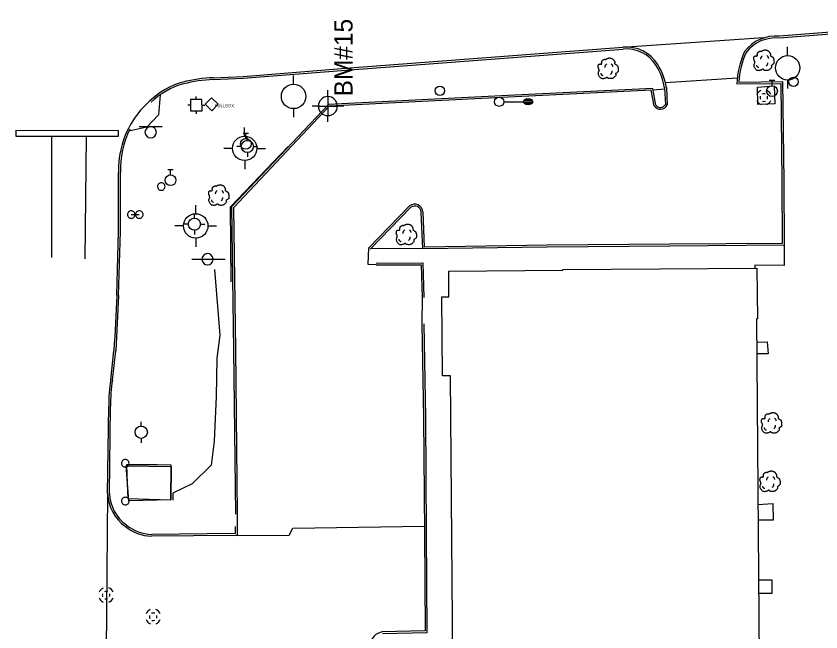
# Model space of a CAD drawing. Extents: x 2145380 to 2157287, y 139568 to 149130.
# Drawn here: x 2145641 to 2145904.9, y 142715.7 to 142917.6 of the extents above; entities that cross this region are included whole.
import ezdxf

# ---------------------------------------------------------------- set-up
doc = ezdxf.new("R2010")
doc.units = 0
for name, color, linetype in [('Default', 7, 'Continuous'), ('SURV_Benchmark', 7, 'Continuous'), ('TOPO_Asphalt', 7, 'Continuous'), ('TOPO_Building', 7, 'Continuous'), ('TOPO_Concrete', 7, 'Continuous'), ('TOPO_Curb Back', 7, 'Continuous'), ('TOPO_DRAIN_Inlet Grate', 7, 'Continuous'), ('TOPO_DRAIN_Manhole', 7, 'Continuous'), ('TOPO_Flowline', 7, 'Continuous'), ('TOPO_Light Pole', 7, 'Continuous'), ('TOPO_Misc', 7, 'Continuous'), ('TOPO_Misc Line', 7, 'Continuous'), ('TOPO_Power Pole', 7, 'Continuous'), ('TOPO_Power Pullbox', 7, 'Continuous'), ('TOPO_Sidewalk', 7, 'Continuous'), ('TOPO_Sign', 7, 'Continuous'), ('TOPO_Traffic Signal', 7, 'Continuous'), ('TOPO_Tree', 7, 'Continuous'), ('TOPO_Wall Freestanding', 7, 'Continuous'), ('TOPO_Water Fire Hydrant', 7, 'Continuous'), ('TOPO_Water Meter', 7, 'Continuous'), ('TOPO_Water Valve', 7, 'Continuous')]:
    doc.layers.add(name, color=color, linetype=linetype)

# ---------------------------------------------------------------- blocks, each defined once
blk = doc.blocks.new('MHEXST')
at = {"layer": 'TOPO_DRAIN_Manhole'}
for centre, radius, start, end in [((-0.1, 0.3), 12.7, 112.9748, 158.2636), ((-0.1, 0.1), 6.35, 157.9722, 204.161), ((-0.1, 0.1), 6.35, 66.1941, 113.691), ((-0.1, 0.3), 12.7, 22.0744, 68.6991), ((-0.1, 0.1), 6.35, 336.8023, 21.4046), ((-0.1, 0.3), 12.7, 202.6921, 248.1938), ((-0.1, 0.1), 6.35, 248.5791, 293.1995), ((-0.1, 0.3), 12.7, 291.7963, 337.3032)]:
    blk.add_arc(centre, radius, start, end, dxfattribs=at)
blk = doc.blocks.new('TRFSIG')
at = {"layer": 'TOPO_Traffic Signal'}
for p, q in [((0.04, 4.66), (0.04, 7.04)), ((-4.7, -0.09), (-7.08, -0.09)), ((0.04, -4.83), (0.04, -7.22)), ((4.79, -0.09), (7.17, -0.09))]:
    blk.add_line(p, q, dxfattribs=at)
blk.add_lwpolyline([(-4.7, -4.85), (4.81, -4.83), (4.79, 4.67), (-4.72, 4.66), (-4.7, -4.85)], dxfattribs=at)
blk = doc.blocks.new('FIRHYD')
at = {"layer": 'TOPO_Water Fire Hydrant'}
for p, q in [((-0.02, 10.16), (-0.03, 17.34)), ((10.16, 0.02), (17.34, 0.03)), ((-10.16, -0.02), (-17.34, -0.03)), ((0.02, -10.16), (0.03, -17.34))]:
    blk.add_line(p, q, dxfattribs=at)
blk.add_circle((0, 0), 10.16, dxfattribs=at)
blk = doc.blocks.new('POST')
at = {"layer": 'TOPO_Misc'}
for start, end in [(89.99996, 180.00004), (179.99996, 270.00004), (359.99996, 90.00004), (269.99996, 0.00004)]:
    blk.add_arc((-0.01, 0.03), 3.16, start, end, dxfattribs=at)
blk = doc.blocks.new('POWPOL')
at = {"layer": 'TOPO_Power Pole'}
for p, q in [((0, 10.16), (0, 17.34)), ((0, -10.16), (0, -17.34))]:
    blk.add_line(p, q, dxfattribs=at)
blk.add_circle((0, 0), 10.16, dxfattribs=at)
blk = doc.blocks.new('LP')
at = {"layer": 'TOPO_Light Pole'}
blk.add_line((3.81, 0), (20.32, 0), dxfattribs=at)
for points in [[(20.32, 0), (27.94, 0)], [(20.32, 0), (23.5, 0)], [(20.83, 1.27), (27.43, 1.27)], [(20.83, 1.27), (23.5, 1.27)], [(23.71, 1.27), (27.43, 1.27)], [(23.71, 0), (27.94, 0)], [(20.83, -1.27), (27.43, -1.27)], [(20.83, -1.27), (23.5, -1.27)], [(23.71, -1.27), (27.43, -1.27)]]:
    blk.add_lwpolyline(points, dxfattribs=at)
blk.add_circle((0, 0), 3.81, dxfattribs=at)
blk.add_ellipse((24.13, 0), major_axis=(3.81, 0), ratio=0.666667, dxfattribs=at)
blk = doc.blocks.new('TREE')
at = {"layer": 'TOPO_Tree'}
for points in [[(-14.1, -0.4), (-14.2, 0.5), (-14.4, 1.4), (-14.6, 2.3), (-14.8, 3.2), (-15.5, 4), (-15.7, 4.9), (-15.8, 5.6), (-15.7, 6.3), (-15.7, 7), (-15.6, 7.9), (-15.7, 8.8), (-15.1, 9.7), (-14.6, 10.4), (-13.8, 10.5), (-13, 10.7), (-12.2, 11), (-11.1, 10), (-10.4, 10.7), (-9.4, 11.7), (-10.3, 13.3), (-9.8, 14.4), (-9.6, 15.1), (-9.3, 15.9), (-8.8, 16.5), (-8.2, 17.3), (-7.5, 17.7), (-6.7, 18.1), (-6.1, 18.4), (-5.6, 18.6), (-5.1, 18.7), (-4.5, 18.7), (-4, 18.5), (-3.5, 18.1)], [(-3.5, 17.6), (-3.1, 18.3), (-2.6, 18.8), (-1.9, 19.2), (-1, 19.7), (-0.2, 20), (0.7, 20.2), (1.6, 20.5), (2.5, 20.8), (3.4, 20.8), (4.1, 20.7), (4.8, 20.5), (5.5, 20.2), (6.4, 19.9), (7.3, 19.7), (8.2, 19.2), (9.4, 18.4), (10, 17.2), (10.8, 16), (11.2, 15.3), (11.6, 14.6), (11.9, 13.9), (12.2, 13.1), (11.4, 12), (11.9, 11.2), (12, 11), (12.2, 10.9), (12.4, 10.7), (12.9, 10.4), (13.5, 10), (14, 9.7), (14.7, 9.2), (15.4, 8.7), (16.1, 8.1), (16.7, 7.5), (16.9, 6.7), (17.1, 6), (17.6, 4.4), (17.7, 2.8), (17.7, 1.2), (17.7, -0.2), (17.8, -2.2), (16.6, -3), (15.5, -3.8), (14.3, -4.6), (13.2, -5.3)], [(13.2, -5.3), (13.3, -5.8), (13.4, -6.3), (13.4, -6.7), (13.8, -8.5), (12.2, -10), (10.8, -11.5), (10, -12.3), (9.1, -12.8), (8.2, -13.1), (6, -13.8), (3.3, -13.6), (1.3, -13.1), (0.5, -12.9), (-0.1, -11.4), (-0.8, -11.5), (-2, -11.6), (-3.3, -12.8), (-4.5, -13.1), (-6.1, -13.5), (-7.8, -14), (-9.3, -13.6), (-11.4, -13.1), (-12.8, -11.4), (-14.1, -9.4), (-15.3, -7.3), (-15.6, -5.1), (-15.1, -3), (-14.9, -1.9), (-13.9, -0.8), (-13.5, 0.1)], [(-4.2, 5.1), (-4.5, 6.1), (-4.3, 7.2), (-3.8, 8.2), (-3.3, 9.3), (-2.7, 10.3), (-1.6, 11)], [(5.9, 11.2), (6.5, 10.7), (7, 10.2), (7.4, 9.5), (7.9, 8.6), (8.3, 7.6), (8.5, 6.6)], [(-11.4, -4.5), (-11.5, -5.4), (-11, -6.3), (-10.1, -7.2), (-9.3, -8), (-8.5, -8.3), (-7.7, -8.1)], [(4.8, -6.3), (5.7, -5.7), (6.3, -4.9), (6.8, -3.9), (7.4, -2.8), (7.6, -1.7), (7.5, -0.6)]]:
    blk.add_open_spline(points, degree=3, dxfattribs=at)
blk = doc.blocks.new('pulbox')
at = {"layer": 'Default'}
blk.add_lwpolyline([(-5.38, -0.01), (-0.02, 5.42), (5.4, 0.06), (0.05, -5.36), (-5.38, -0.01)], dxfattribs=at)
blk.add_text('PULLBOX', height=2.54, dxfattribs=at).set_placement((2.54, -2.54))
blk = doc.blocks.new('WTRMTR')
at = {"layer": 'Default'}
blk.add_circle((0, 0), 3.89, dxfattribs=at)
blk = doc.blocks.new('WATVAL')
at = {"layer": 'Default'}
for p, q in [((-2.25, 9), (2.25, 9)), ((0, 4.5), (0, 9))]:
    blk.add_line(p, q, dxfattribs=at)
blk.add_circle((0, 0), 4.5, dxfattribs=at)
blk = doc.blocks.new('BM')
at = {"layer": 'SURV_Benchmark'}
for p, q in [((0, 2.49), (0, 4.15)), ((-2.49, 0), (-4.16, 0)), ((4.16, 0), (2.49, 0)), ((0, -4.16), (0, -2.49))]:
    blk.add_line(p, q, dxfattribs=at)
for points in [[(0, 2.49), (0, 2.49), (0, 0), (2.49, 0), (2.49, 0), (2.49, 0)], [(0, 2.49), (0, 2.49), (0, 0), (2.49, 0), (2.49, 0), (2.49, 0), (2.49, 0)], [(-2.5, 0), (-2.49, 0), (0, 0), (0, -2.49), (0, -2.49)], [(-2.5, 0), (-2.49, 0), (0, 0), (0, -2.49), (0, -2.49)]]:
    blk.add_lwpolyline(points, dxfattribs=at)
for start, end in [(90.0638, 180.0068), (0.0638, 90.0068), (0.0638, 90.0068), (180.0638, 270.0068), (180.0638, 270.0068), (269.9472, 359.9927)]:
    blk.add_arc((0, 0), 2.5, start, end, dxfattribs=at)

msp = doc.modelspace()

# ---------------------------------------------------------------- linework, layer by layer
at = {"layer": 'TOPO_Asphalt'}
for p, q in [((2145886.13, 142910.45), (2145841.37, 142907.47)), ((2145877.51, 142897.29), (2145853.93, 142895.76)), ((2145774.14, 142825.35), (2145774.11, 142816.75)), ((2145671.02, 142761.1), (2145670.5, 142699.12)), ((2145713.58, 142754.35), (2145713.49, 142750.35))]:
    msp.add_line(p, q, dxfattribs=at)
for points in [[(2145759.07, 142836.04), (2145756.5, 142836.19), (2145756.67, 142841.6)], [(2145713.48, 142747.28), (2145730.63, 142747.43), (2145731.81, 142749.72), (2145774.89, 142750.39)]]:
    msp.add_lwpolyline(points, dxfattribs=at)
msp.add_arc((2145705.41, 142866.44), 31.07, 131.2509, 152.4834, dxfattribs=at)
at = {"layer": 'TOPO_Building'}
msp.add_lwpolyline([(2145884.64, 142706.75), (2145784.22, 142705.97), (2145783.49, 142799.65), (2145780.88, 142799.63), (2145780.68, 142825.53), (2145782.96, 142825.55), (2145782.9, 142834.03), (2145820.28, 142834.32), (2145820.28, 142834.52), (2145883.96, 142835.02), (2145884.09, 142818.36), (2145883.77, 142818.35)], close=True, dxfattribs=at)
at = {"layer": 'TOPO_Concrete'}
for p in [(2145849.96, 142893.38), (2145853.67, 142893.7)]:
    msp.add_line(p, (2145849.97, 142893.35), dxfattribs=at)
for points in [[(2145884.29, 142888.65), (2145884.12, 142894.3), (2145889.62, 142894.74), (2145889.85, 142888.86), (2145884.29, 142888.65)], [(2145691.76, 142759.04), (2145678.01, 142758.73), (2145677.16, 142770.2), (2145691.84, 142769.99), (2145691.76, 142759.04)], [(2145687.34, 142770.51), (2145677.29, 142770.48), (2145677.43, 142764.27), (2145677.71, 142759.42), (2145691.77, 142759.01)]]:
    msp.add_lwpolyline(points, dxfattribs=at)
at = {"layer": 'TOPO_Curb Back'}
for points in [[(2146086.5, 142923.91), (2146062.14, 142922.81), (2146006.06, 142919.37), (2145953.33, 142915.85), (2145891.26, 142911.02)], [(2146086.5, 142923.31), (2146062.17, 142922.21), (2146006.1, 142918.78), (2145953.37, 142915.25), (2145891.26, 142910.41)], [(2145705.69, 142897.41), (2145715.49, 142897.82), (2145750.51, 142900.64), (2145840, 142907.41)], [(2145705.71, 142896.81), (2145715.53, 142897.22), (2145750.55, 142900.04), (2145840.06, 142906.82)], [(2145878.01, 142895.99), (2145892.37, 142896.17), (2145892.74, 142863.48), (2145892.85, 142842.52), (2145855.35, 142842.22), (2145815.14, 142841.9), (2145774.4, 142841.27), (2145773.86, 142853.39)], [(2145850.79, 142888.46), (2145849.77, 142893.91), (2145804.61, 142891.73), (2145743.47, 142888.67), (2145711.71, 142855.05), (2145712.36, 142808.25), (2145712.98, 142754.34)], [(2145850.22, 142888.24), (2145849.28, 142893.29), (2145804.64, 142891.13), (2145743.74, 142888.08), (2145712.31, 142854.81), (2145712.96, 142808.26), (2145713.58, 142754.35)], [(2145877.38, 142895.38), (2145891.78, 142895.57), (2145892.14, 142863.48), (2145892.25, 142843.11), (2145855.35, 142842.82), (2145815.14, 142842.5), (2145774.97, 142841.88), (2145774.46, 142853.43)], [(2145853.65, 142894.1), (2145853.93, 142888.65)], [(2145854.25, 142894.16), (2145854.54, 142888.53)], [(2145711.55, 142830.49), (2145711.32, 142855.13), (2145730.22, 142874.89)], [(2145674.05, 142826.07), (2145674.67, 142847.01), (2145674.66, 142866.3)], [(2145674.65, 142826.04), (2145675.27, 142847), (2145675.26, 142866.31)], [(2145770.08, 142855.38), (2145756.67, 142841.6)], [(2145770.48, 142854.93), (2145757.1, 142841.18)], [(2145759.07, 142836.64), (2145774.39, 142836.67), (2145774.74, 142825.37)], [(2145759.07, 142836.04), (2145773.81, 142836.07), (2145774.14, 142825.35)], [(2145774.11, 142816.75), (2145774.65, 142785.86), (2145774.9, 142748.25), (2145775.16, 142716.03), (2145761.11, 142715.71)], [(2145774.71, 142816.76), (2145775.25, 142785.87), (2145775.5, 142748.26), (2145775.76, 142715.44), (2145761.17, 142715.11)], [(2145672.06, 142798.38), (2145673.14, 142807.9)], [(2145672.65, 142798.3), (2145673.74, 142807.85)], [(2145671.02, 142761.1), (2145671.4, 142789.68)], [(2145671.62, 142761.11), (2145672, 142789.68)], [(2145713.5, 142750.31), (2145713.48, 142747.28), (2145712.97, 142747.32), (2145685.42, 142747.1)], [(2145712.9, 142750.32), (2145712.9, 142748.9), (2145712.86, 142747.98), (2145685.43, 142747.7)]]:
    msp.add_lwpolyline(points, dxfattribs=at)
for centre, radius, start, end in [((2145890.08, 142898.28), 12.8, 84.6897, 142.941), ((2145890.08, 142898.28), 12.2, 84.4518, 142.6291), ((2145841.16, 142895.41), 12.06, 31.8502, 95.4973), ((2145841.16, 142895.41), 11.46, 31.8468, 95.5275), ((2145905.51, 142894.38), 28.15, 155.6481, 177.9548), ((2145905.51, 142894.38), 27.55, 155.788, 176.6443), ((2145834.14, 142890.99), 19.76, 9.0341, 31.9817), ((2145834.14, 142890.99), 20.36, 8.9444, 31.9797), ((2145702.16, 142872.13), 24.69, 105.0623, 134.2848), ((2145707.07, 142852.94), 44.49, 91.7794, 104.7442), ((2145707.07, 142852.94), 43.89, 91.7752, 104.742), ((2145702.16, 142872.13), 24.09, 105.0663, 134.2848), ((2145852.31, 142889.5), 2.43, 211.1477, 336.5758), ((2145852.31, 142889.5), 1.83, 214.3157, 332.4691), ((2145704.6, 142867.3), 29.96, 153.2161, 181.9143), ((2145704.6, 142867.3), 29.36, 153.2161, 181.9334), ((2145771.74, 142853.22), 2.72, 4.3097, 127.5899), ((2145771.74, 142853.22), 2.12, 4.5437, 126.5018), ((2161048.92, 142043.63), 15394.76, 177.086696, 177.154392), ((2161048.93, 142043.63), 15394.17, 177.086673, 177.154463), ((2145721.13, 142790.33), 49.73, 170.6762, 180.7386), ((2145721.13, 142790.33), 49.13, 170.659, 180.7478), ((2145685.07, 142761.73), 14.06, 182.5625, 234.441), ((2145685.07, 142761.73), 13.46, 182.6359, 234.5179), ((2145685.94, 142761.46), 13.78, 230.9156, 267.8614), ((2145685.94, 142761.46), 14.38, 230.9908, 267.9161), ((2145761.93, 142710.85), 4.93, 99.5713, 169.4602)]:
    msp.add_arc(centre, radius, start, end, dxfattribs=at)
at = {"layer": 'TOPO_DRAIN_Inlet Grate'}
msp.add_line((2145678.79, 142852.54), (2145681.45, 142852.55), dxfattribs=at)
at = {"layer": 'TOPO_Flowline'}
msp.add_lwpolyline([(2145706.15, 142834.57), (2145707.84, 142813.02), (2145706.89, 142805.44), (2145706.62, 142792.9), (2145705.97, 142778.22), (2145704.97, 142770.4), (2145698.73, 142764.31), (2145692.47, 142761.25), (2145692.48, 142758.96)], dxfattribs=at)
at = {"layer": 'TOPO_Misc Line'}
for p, q in [((2145652.61, 142878.17), (2145652.64, 142838.47)), ((2145664, 142878.16), (2145663.55, 142838))]:
    msp.add_line(p, q, dxfattribs=at)
msp.add_lwpolyline([(2145641.05, 142880.2), (2145674.51, 142880.15), (2145674.5, 142878.14), (2145641.05, 142878.19)], close=True, dxfattribs=at)
at = {"layer": 'TOPO_Sidewalk'}
msp.add_line((2145774.4, 142841.27), (2145757.32, 142841.4), dxfattribs=at)
for points in [[(2145688.33, 142891.85), (2145687.71, 142885.28), (2145683.92, 142881.18), (2145678.06, 142879.86)], [(2145892.85, 142842.52), (2145892.92, 142835.87), (2145883.23, 142835.92), (2145883.23, 142835.01)], [(2145883.83, 142810.75), (2145887.34, 142810.78), (2145887.61, 142806.89), (2145883.86, 142806.86)], [(2145884.25, 142757.51), (2145889.14, 142757.83), (2145889.25, 142752.3), (2145884.29, 142752.3)], [(2145884.44, 142732.77), (2145888.86, 142732.8), (2145888.82, 142728.29), (2145884.48, 142728.26)]]:
    msp.add_lwpolyline(points, dxfattribs=at)
at = {"layer": 'TOPO_Sign'}
for points in [[(2145681.43, 142881.4), (2145688.93, 142881.4)], [(2145685.18, 142881.4), (2145685.18, 142881.4)], [(2145683.31, 142879.53), (2145683.31, 142879.53)], [(2145685.18, 142877.66), (2145685.18, 142877.66)], [(2145687.05, 142879.53), (2145687.05, 142879.53)], [(2145698.67, 142837.88), (2145709.55, 142837.94)]]:
    msp.add_lwpolyline(points, dxfattribs=at)
for centre, radius, start, end in [((2145685.18, 142879.53), 1.87, 90, 180), ((2145685.18, 142879.53), 1.87, 360, 90), ((2145685.18, 142879.53), 1.87, 180, 270), ((2145685.18, 142879.53), 1.87, 270, 0), ((2145703.81, 142837.9), 1.84, 47.4196, 227.4196), ((2145703.81, 142837.9), 1.84, 227.4196, 47.4196)]:
    msp.add_arc(centre, radius, start, end, dxfattribs=at)
at = {"layer": 'TOPO_Wall Freestanding'}
msp.add_lwpolyline([(2145691.77, 142759.01), (2145691.84, 142770.39), (2145687.34, 142770.51)], dxfattribs=at)

# ---------------------------------------------------------------- block references
at = {"layer": 'SURV_Benchmark', "xscale": 1.25, "yscale": 1.25}
msp.add_blockref('BM', (2145743.27, 142888.11), dxfattribs=at)
at = {"layer": 'TOPO_DRAIN_Manhole', "xscale": 0.19685000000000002, "yscale": 0.19685000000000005}
for p in [(2145886.23, 142890.9), (2145670.59, 142727.74), (2145686.01, 142720.65)]:
    msp.add_blockref('MHEXST', p, dxfattribs=at)
at = {"layer": 'TOPO_Light Pole', "xscale": 0.39370000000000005, "yscale": 0.3937000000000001}
msp.add_blockref('LP', (2145799.42, 142889.53), dxfattribs=at)
at = {"layer": 'TOPO_Misc', "xscale": 0.39370000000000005, "yscale": 0.3937000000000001}
for p in [(2145688.64, 142861.73), (2145678.79, 142852.54), (2145681.45, 142852.55), (2145676.84, 142770.99), (2145676.87, 142758.59)]:
    msp.add_blockref('POST', p, dxfattribs=at)
at = {"layer": 'TOPO_Power Pole'}
for p, xscale, yscale in [((2145894.02, 142900.67), 0.39370000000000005, 0.3937000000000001), ((2145732.02, 142891.28), 0.39370000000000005, 0.3937000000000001), ((2145682.08, 142781.17), 0.19685000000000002, 0.19685000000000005)]:
    msp.add_blockref('POWPOL', p, dxfattribs=dict(at, xscale=xscale, yscale=yscale))
at = {"layer": 'TOPO_Power Pullbox', "xscale": 0.39370000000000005, "yscale": 0.3937000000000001}
msp.add_blockref('pulbox', (2145705.16, 142888.71), dxfattribs=at)
at = {"layer": 'TOPO_Traffic Signal', "xscale": 0.39370000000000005, "yscale": 0.3937000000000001}
msp.add_blockref('TRFSIG', (2145700.11, 142888.46), dxfattribs=at)
at = {"layer": 'TOPO_Tree', "xscale": 0.19685000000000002, "yscale": 0.19685000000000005}
for p in [(2145886.05, 142902.46), (2145835, 142899.8), (2145707.31, 142858.26), (2145768.81, 142845.35), (2145888.57, 142783.57), (2145888.04, 142764.41)]:
    msp.add_blockref('TREE', p, dxfattribs=at)
at = {"layer": 'TOPO_Water Fire Hydrant'}
for p, xscale, yscale in [((2145715.99, 142874.25), 0.39370000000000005, 0.3937000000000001), ((2145716.86, 142874.85), 0.19685000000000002, 0.19685000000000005), ((2145699.94, 142848.83), 0.39370000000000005, 0.3937000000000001), ((2145699.5, 142849.39), 0.19685000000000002, 0.19685000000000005)]:
    msp.add_blockref('FIRHYD', p, dxfattribs=dict(at, xscale=xscale, yscale=yscale))
at = {"layer": 'TOPO_Water Meter', "xscale": 0.39370000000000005, "yscale": 0.3937000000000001}
for p in [(2145895.96, 142896.09), (2145780.01, 142893.13)]:
    msp.add_blockref('WTRMTR', p, dxfattribs=at)
at = {"layer": 'TOPO_Water Valve', "xscale": 0.39370000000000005, "yscale": 0.3937000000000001}
for p in [(2145888.89, 142893.04), (2145716.36, 142875.73), (2145691.69, 142863.82)]:
    msp.add_blockref('WATVAL', p, dxfattribs=at)

# ---------------------------------------------------------------- texts
at = {"layer": 'SURV_Benchmark'}
msp.add_text('BM#15', height=6, rotation=90, dxfattribs=at).set_placement((2145751.36, 142891.29))

doc.saveas('drawing.dxf')
